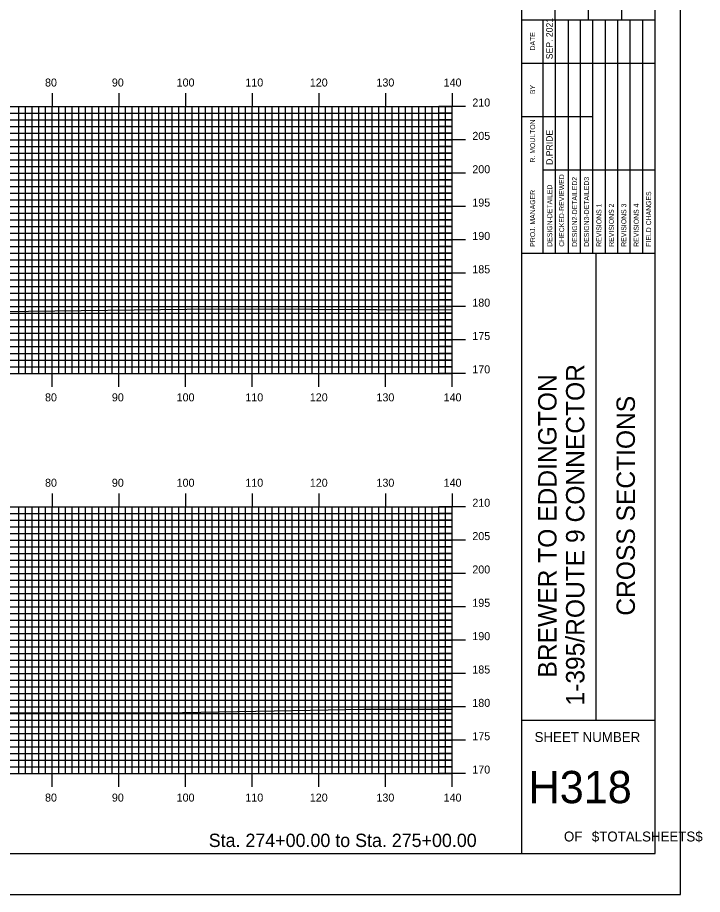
# Model space of a CAD drawing. Extents: x 1809406 to 1809749, y 442591 to 442811.
# Drawn here: x 1809646.7 to 1809749.3, y 442590.5 to 442722 of the extents above; entities that cross this region are included whole.
import ezdxf

# ---------------------------------------------------------------- set-up
doc = ezdxf.new("R2010")
doc.units = 0
for name, color, linetype in [('BORDER', 7, 'Continuous'), ('H_V ANNOTATION', 7, 'Continuous'), ('MAJOR', 7, 'Continuous'), ('MINOR', 7, 'Continuous'), ('PLOT BOUNDARY', 7, 'Continuous'), ('S_Roadway_Centerline', 7, 'Continuous')]:
    doc.layers.add(name, color=color, linetype=linetype)

msp = doc.modelspace()

# ---------------------------------------------------------------- linework, layer by layer
at = {"layer": 'BORDER'}
for p, q in [((1809722.24, 442596.67), (1809722.24, 442806.67)), ((1809727.24, 442721.67), (1809727.24, 442738.97)), ((1809732.24, 442721.67), (1809732.24, 442738.97)), ((1809737.24, 442721.67), (1809737.24, 442738.97)), ((1809722.24, 442721.67), (1809742.24, 442721.67)), ((1809722.24, 442686.67), (1809742.24, 442686.67)), ((1809733.42, 442616.67), (1809733.42, 442686.67)), ((1809722.24, 442616.67), (1809742.24, 442616.67))]:
    msp.add_line(p, q, dxfattribs=at)
msp.add_lwpolyline([(1809422.24, 442596.67), (1809742.24, 442596.67), (1809742.24, 442806.67), (1809422.24, 442806.67)], close=True, dxfattribs=at)
for points in [[(1809725.47, 442715.17), (1809725.47, 442721.67)], [(1809727.33, 442686.68), (1809727.33, 442721.67)], [(1809729.2, 442721.67), (1809729.2, 442686.68)], [(1809731.06, 442686.68), (1809731.06, 442721.67)], [(1809732.92, 442686.68), (1809732.92, 442721.67)], [(1809734.79, 442686.68), (1809734.79, 442721.67)], [(1809736.65, 442686.68), (1809736.65, 442721.67)], [(1809738.51, 442686.68), (1809738.51, 442721.67)], [(1809740.38, 442686.68), (1809740.38, 442721.67)], [(1809725.47, 442686.68), (1809725.47, 442720.26)], [(1809722.24, 442715.17), (1809742.24, 442715.17)], [(1809722.24, 442707.17), (1809725.47, 442707.17)], [(1809725.47, 442707.17), (1809732.92, 442707.17)], [(1809725.47, 442699.17), (1809742.24, 442699.17)]]:
    msp.add_lwpolyline(points, dxfattribs=at)
at = {"layer": 'MAJOR'}
for p, q in [((1809651.84, 442710.67), (1809651.84, 442708.67)), ((1809661.84, 442710.67), (1809661.84, 442708.67)), ((1809671.84, 442710.67), (1809671.84, 442708.67)), ((1809681.84, 442710.67), (1809681.84, 442708.67)), ((1809691.84, 442710.67), (1809691.84, 442708.67)), ((1809701.84, 442710.67), (1809701.84, 442708.67)), ((1809711.84, 442710.67), (1809711.84, 442708.67)), ((1809431.84, 442708.67), (1809711.84, 442708.67)), ((1809431.84, 442708.67), (1809711.84, 442708.67)), ((1809651.84, 442668.67), (1809651.84, 442708.67)), ((1809661.84, 442668.67), (1809661.84, 442708.67)), ((1809671.84, 442668.67), (1809671.84, 442708.67)), ((1809681.84, 442668.67), (1809681.84, 442708.67)), ((1809691.84, 442668.67), (1809691.84, 442708.67)), ((1809701.84, 442668.67), (1809701.84, 442708.67)), ((1809713.84, 442708.67), (1809709.83, 442708.67)), ((1809711.84, 442668.67), (1809711.84, 442708.67)), ((1809711.84, 442668.67), (1809711.84, 442708.67)), ((1809431.84, 442703.67), (1809711.84, 442703.67)), ((1809713.84, 442703.67), (1809709.83, 442703.67)), ((1809431.84, 442698.67), (1809711.84, 442698.67)), ((1809713.84, 442698.67), (1809709.83, 442698.67)), ((1809431.84, 442693.67), (1809711.84, 442693.67)), ((1809713.84, 442693.67), (1809709.83, 442693.67)), ((1809431.84, 442688.67), (1809711.84, 442688.67)), ((1809713.84, 442688.67), (1809709.83, 442688.67)), ((1809431.84, 442683.67), (1809711.84, 442683.67)), ((1809713.84, 442683.67), (1809709.83, 442683.67)), ((1809431.84, 442678.67), (1809711.84, 442678.67)), ((1809713.84, 442678.67), (1809709.83, 442678.67)), ((1809431.84, 442673.67), (1809711.84, 442673.67)), ((1809713.84, 442673.67), (1809709.83, 442673.67)), ((1809431.84, 442668.67), (1809711.84, 442668.67)), ((1809431.84, 442668.67), (1809711.84, 442668.67)), ((1809651.84, 442666.66), (1809651.84, 442668.67)), ((1809661.84, 442666.66), (1809661.84, 442668.67)), ((1809671.84, 442666.66), (1809671.84, 442668.67)), ((1809681.84, 442666.66), (1809681.84, 442668.67)), ((1809691.84, 442666.66), (1809691.84, 442668.67)), ((1809701.84, 442666.66), (1809701.84, 442668.67)), ((1809713.84, 442668.67), (1809709.83, 442668.67)), ((1809711.84, 442666.66), (1809711.84, 442668.67)), ((1809651.84, 442650.67), (1809651.84, 442648.67)), ((1809661.84, 442650.67), (1809661.84, 442648.67)), ((1809671.84, 442650.67), (1809671.84, 442648.67)), ((1809681.84, 442650.67), (1809681.84, 442648.67)), ((1809691.84, 442650.67), (1809691.84, 442648.67)), ((1809701.84, 442650.67), (1809701.84, 442648.67)), ((1809711.84, 442650.67), (1809711.84, 442648.67)), ((1809431.84, 442648.67), (1809711.84, 442648.67)), ((1809431.84, 442648.67), (1809711.84, 442648.67)), ((1809651.84, 442608.67), (1809651.84, 442648.67)), ((1809661.84, 442608.67), (1809661.84, 442648.67)), ((1809671.84, 442608.67), (1809671.84, 442648.67)), ((1809681.84, 442608.67), (1809681.84, 442648.67)), ((1809691.84, 442608.67), (1809691.84, 442648.67)), ((1809701.84, 442608.67), (1809701.84, 442648.67)), ((1809713.84, 442648.67), (1809709.83, 442648.67)), ((1809711.84, 442608.67), (1809711.84, 442648.67)), ((1809711.84, 442608.67), (1809711.84, 442648.67)), ((1809431.84, 442643.67), (1809711.84, 442643.67)), ((1809713.84, 442643.67), (1809709.83, 442643.67)), ((1809431.84, 442638.67), (1809711.84, 442638.67)), ((1809713.84, 442638.67), (1809709.83, 442638.67)), ((1809431.84, 442633.67), (1809711.84, 442633.67)), ((1809713.84, 442633.67), (1809709.83, 442633.67)), ((1809431.84, 442628.67), (1809711.84, 442628.67)), ((1809713.84, 442628.67), (1809709.83, 442628.67)), ((1809431.84, 442623.67), (1809711.84, 442623.67)), ((1809713.84, 442623.67), (1809709.83, 442623.67)), ((1809431.84, 442618.67), (1809711.84, 442618.67)), ((1809713.84, 442618.67), (1809709.83, 442618.67)), ((1809431.84, 442613.67), (1809711.84, 442613.67)), ((1809713.84, 442613.67), (1809709.83, 442613.67)), ((1809431.84, 442608.67), (1809711.84, 442608.67)), ((1809431.84, 442608.67), (1809711.84, 442608.67)), ((1809651.84, 442606.66), (1809651.84, 442608.67)), ((1809661.84, 442606.66), (1809661.84, 442608.67)), ((1809671.84, 442606.66), (1809671.84, 442608.67)), ((1809681.84, 442606.66), (1809681.84, 442608.67)), ((1809691.84, 442606.66), (1809691.84, 442608.67)), ((1809701.84, 442606.66), (1809701.84, 442608.67)), ((1809713.84, 442608.67), (1809709.83, 442608.67)), ((1809711.84, 442606.66), (1809711.84, 442608.67))]:
    msp.add_line(p, q, dxfattribs=at)
at = {"layer": 'MINOR'}
for p, q in [((1809646.84, 442668.67), (1809646.84, 442708.67)), ((1809647.84, 442668.67), (1809647.84, 442708.67)), ((1809648.84, 442668.67), (1809648.84, 442708.67)), ((1809649.84, 442668.67), (1809649.84, 442708.67)), ((1809650.84, 442668.67), (1809650.84, 442708.67)), ((1809652.84, 442668.67), (1809652.84, 442708.67)), ((1809653.84, 442668.67), (1809653.84, 442708.67)), ((1809654.84, 442668.67), (1809654.84, 442708.67)), ((1809655.84, 442668.67), (1809655.84, 442708.67)), ((1809656.84, 442668.67), (1809656.84, 442708.67)), ((1809657.84, 442668.67), (1809657.84, 442708.67)), ((1809658.84, 442668.67), (1809658.84, 442708.67)), ((1809659.84, 442668.67), (1809659.84, 442708.67)), ((1809660.84, 442668.67), (1809660.84, 442708.67)), ((1809662.84, 442668.67), (1809662.84, 442708.67)), ((1809663.84, 442668.67), (1809663.84, 442708.67)), ((1809664.84, 442668.67), (1809664.84, 442708.67)), ((1809665.84, 442668.67), (1809665.84, 442708.67)), ((1809666.84, 442668.67), (1809666.84, 442708.67)), ((1809667.84, 442668.67), (1809667.84, 442708.67)), ((1809668.84, 442668.67), (1809668.84, 442708.67)), ((1809669.84, 442668.67), (1809669.84, 442708.67)), ((1809670.84, 442668.67), (1809670.84, 442708.67)), ((1809672.84, 442668.67), (1809672.84, 442708.67)), ((1809673.84, 442668.67), (1809673.84, 442708.67)), ((1809674.84, 442668.67), (1809674.84, 442708.67)), ((1809675.84, 442668.67), (1809675.84, 442708.67)), ((1809676.84, 442668.67), (1809676.84, 442708.67)), ((1809677.84, 442668.67), (1809677.84, 442708.67)), ((1809678.84, 442668.67), (1809678.84, 442708.67)), ((1809679.84, 442668.67), (1809679.84, 442708.67)), ((1809680.84, 442668.67), (1809680.84, 442708.67)), ((1809682.84, 442668.67), (1809682.84, 442708.67)), ((1809683.84, 442668.67), (1809683.84, 442708.67)), ((1809684.84, 442668.67), (1809684.84, 442708.67)), ((1809685.84, 442668.67), (1809685.84, 442708.67)), ((1809686.84, 442668.67), (1809686.84, 442708.67)), ((1809687.84, 442668.67), (1809687.84, 442708.67)), ((1809688.84, 442668.67), (1809688.84, 442708.67)), ((1809689.84, 442668.67), (1809689.84, 442708.67)), ((1809690.84, 442668.67), (1809690.84, 442708.67)), ((1809692.84, 442668.67), (1809692.84, 442708.67)), ((1809693.84, 442668.67), (1809693.84, 442708.67)), ((1809694.84, 442668.67), (1809694.84, 442708.67)), ((1809695.84, 442668.67), (1809695.84, 442708.67)), ((1809696.84, 442668.67), (1809696.84, 442708.67)), ((1809697.84, 442668.67), (1809697.84, 442708.67)), ((1809698.84, 442668.67), (1809698.84, 442708.67)), ((1809699.84, 442668.67), (1809699.84, 442708.67)), ((1809700.84, 442668.67), (1809700.84, 442708.67)), ((1809702.84, 442668.67), (1809702.84, 442708.67)), ((1809703.84, 442668.67), (1809703.84, 442708.67)), ((1809704.84, 442668.67), (1809704.84, 442708.67)), ((1809705.84, 442668.67), (1809705.84, 442708.67)), ((1809706.84, 442668.67), (1809706.84, 442708.67)), ((1809707.84, 442668.67), (1809707.84, 442708.67)), ((1809708.84, 442668.67), (1809708.84, 442708.67)), ((1809709.84, 442668.67), (1809709.84, 442708.67)), ((1809710.84, 442668.67), (1809710.84, 442708.67)), ((1809431.84, 442707.67), (1809711.84, 442707.67)), ((1809711.84, 442707.67), (1809709.83, 442707.67)), ((1809431.84, 442706.67), (1809711.84, 442706.67)), ((1809431.84, 442705.67), (1809711.84, 442705.67)), ((1809711.84, 442706.67), (1809709.83, 442706.67)), ((1809711.84, 442705.67), (1809709.83, 442705.67)), ((1809431.84, 442704.67), (1809711.84, 442704.67)), ((1809711.84, 442704.67), (1809709.83, 442704.67)), ((1809431.84, 442702.67), (1809711.84, 442702.67)), ((1809431.84, 442701.67), (1809711.84, 442701.67)), ((1809711.84, 442702.67), (1809709.83, 442702.67)), ((1809711.84, 442701.67), (1809709.83, 442701.67)), ((1809431.84, 442700.67), (1809711.84, 442700.67)), ((1809711.84, 442700.67), (1809709.83, 442700.67)), ((1809431.84, 442699.67), (1809711.84, 442699.67)), ((1809711.84, 442699.67), (1809709.83, 442699.67)), ((1809431.84, 442697.67), (1809711.84, 442697.67)), ((1809711.84, 442697.67), (1809709.83, 442697.67)), ((1809431.84, 442696.67), (1809711.84, 442696.67)), ((1809711.84, 442696.67), (1809709.83, 442696.67)), ((1809431.84, 442695.67), (1809711.84, 442695.67)), ((1809711.84, 442695.67), (1809709.83, 442695.67)), ((1809431.84, 442694.67), (1809711.84, 442694.67)), ((1809711.84, 442694.67), (1809709.83, 442694.67)), ((1809431.84, 442692.67), (1809711.84, 442692.67)), ((1809711.84, 442692.67), (1809709.83, 442692.67)), ((1809431.84, 442691.67), (1809711.84, 442691.67)), ((1809711.84, 442691.67), (1809709.83, 442691.67)), ((1809431.84, 442690.67), (1809711.84, 442690.67)), ((1809711.84, 442690.67), (1809709.83, 442690.67)), ((1809431.84, 442689.67), (1809711.84, 442689.67)), ((1809711.84, 442689.67), (1809709.83, 442689.67)), ((1809431.84, 442687.67), (1809711.84, 442687.67)), ((1809711.84, 442687.67), (1809709.83, 442687.67)), ((1809431.84, 442686.67), (1809711.84, 442686.67)), ((1809711.84, 442686.67), (1809709.83, 442686.67)), ((1809431.84, 442685.67), (1809711.84, 442685.67)), ((1809431.84, 442684.67), (1809711.84, 442684.67)), ((1809711.84, 442685.67), (1809709.83, 442685.67)), ((1809711.84, 442684.67), (1809709.83, 442684.67)), ((1809431.84, 442682.67), (1809711.84, 442682.67)), ((1809711.84, 442682.67), (1809709.83, 442682.67)), ((1809431.84, 442681.67), (1809711.84, 442681.67)), ((1809431.84, 442680.67), (1809711.84, 442680.67)), ((1809711.84, 442681.67), (1809709.83, 442681.67)), ((1809711.84, 442680.67), (1809709.83, 442680.67)), ((1809431.84, 442679.67), (1809711.84, 442679.67)), ((1809711.84, 442679.67), (1809709.83, 442679.67)), ((1809431.84, 442677.67), (1809711.84, 442677.67)), ((1809431.84, 442676.67), (1809711.84, 442676.67)), ((1809711.84, 442677.67), (1809709.83, 442677.67)), ((1809711.84, 442676.67), (1809709.83, 442676.67)), ((1809431.84, 442675.67), (1809711.84, 442675.67)), ((1809711.84, 442675.67), (1809709.83, 442675.67)), ((1809431.84, 442674.67), (1809711.84, 442674.67)), ((1809711.84, 442674.67), (1809709.83, 442674.67)), ((1809431.84, 442672.67), (1809711.84, 442672.67)), ((1809711.84, 442672.67), (1809709.83, 442672.67)), ((1809431.84, 442671.67), (1809711.84, 442671.67)), ((1809711.84, 442671.67), (1809709.83, 442671.67)), ((1809431.84, 442670.67), (1809711.84, 442670.67)), ((1809711.84, 442670.67), (1809709.83, 442670.67)), ((1809431.84, 442669.67), (1809711.84, 442669.67)), ((1809711.84, 442669.67), (1809709.83, 442669.67)), ((1809431.84, 442647.67), (1809711.84, 442647.67)), ((1809646.84, 442608.67), (1809646.84, 442648.67)), ((1809647.84, 442608.67), (1809647.84, 442648.67)), ((1809648.84, 442608.67), (1809648.84, 442648.67)), ((1809649.84, 442608.67), (1809649.84, 442648.67)), ((1809650.84, 442608.67), (1809650.84, 442648.67)), ((1809652.84, 442608.67), (1809652.84, 442648.67)), ((1809653.84, 442608.67), (1809653.84, 442648.67)), ((1809654.84, 442608.67), (1809654.84, 442648.67)), ((1809655.84, 442608.67), (1809655.84, 442648.67)), ((1809656.84, 442608.67), (1809656.84, 442648.67)), ((1809657.84, 442608.67), (1809657.84, 442648.67)), ((1809658.84, 442608.67), (1809658.84, 442648.67)), ((1809659.84, 442608.67), (1809659.84, 442648.67)), ((1809660.84, 442608.67), (1809660.84, 442648.67)), ((1809662.84, 442608.67), (1809662.84, 442648.67)), ((1809663.84, 442608.67), (1809663.84, 442648.67)), ((1809664.84, 442608.67), (1809664.84, 442648.67)), ((1809665.84, 442608.67), (1809665.84, 442648.67)), ((1809666.84, 442608.67), (1809666.84, 442648.67)), ((1809667.84, 442608.67), (1809667.84, 442648.67)), ((1809668.84, 442608.67), (1809668.84, 442648.67)), ((1809669.84, 442608.67), (1809669.84, 442648.67)), ((1809670.84, 442608.67), (1809670.84, 442648.67)), ((1809672.84, 442608.67), (1809672.84, 442648.67)), ((1809673.84, 442608.67), (1809673.84, 442648.67)), ((1809674.84, 442608.67), (1809674.84, 442648.67)), ((1809675.84, 442608.67), (1809675.84, 442648.67)), ((1809676.84, 442608.67), (1809676.84, 442648.67)), ((1809677.84, 442608.67), (1809677.84, 442648.67)), ((1809678.84, 442608.67), (1809678.84, 442648.67)), ((1809679.84, 442608.67), (1809679.84, 442648.67)), ((1809680.84, 442608.67), (1809680.84, 442648.67)), ((1809682.84, 442608.67), (1809682.84, 442648.67)), ((1809683.84, 442608.67), (1809683.84, 442648.67)), ((1809684.84, 442608.67), (1809684.84, 442648.67)), ((1809685.84, 442608.67), (1809685.84, 442648.67)), ((1809686.84, 442608.67), (1809686.84, 442648.67)), ((1809687.84, 442608.67), (1809687.84, 442648.67)), ((1809688.84, 442608.67), (1809688.84, 442648.67)), ((1809689.84, 442608.67), (1809689.84, 442648.67)), ((1809690.84, 442608.67), (1809690.84, 442648.67)), ((1809692.84, 442608.67), (1809692.84, 442648.67)), ((1809693.84, 442608.67), (1809693.84, 442648.67)), ((1809694.84, 442608.67), (1809694.84, 442648.67)), ((1809695.84, 442608.67), (1809695.84, 442648.67)), ((1809696.84, 442608.67), (1809696.84, 442648.67)), ((1809697.84, 442608.67), (1809697.84, 442648.67)), ((1809698.84, 442608.67), (1809698.84, 442648.67)), ((1809699.84, 442608.67), (1809699.84, 442648.67)), ((1809700.84, 442608.67), (1809700.84, 442648.67)), ((1809702.84, 442608.67), (1809702.84, 442648.67)), ((1809703.84, 442608.67), (1809703.84, 442648.67)), ((1809704.84, 442608.67), (1809704.84, 442648.67)), ((1809705.84, 442608.67), (1809705.84, 442648.67)), ((1809706.84, 442608.67), (1809706.84, 442648.67)), ((1809707.84, 442608.67), (1809707.84, 442648.67)), ((1809708.84, 442608.67), (1809708.84, 442648.67)), ((1809711.84, 442647.67), (1809709.83, 442647.67)), ((1809709.84, 442608.67), (1809709.84, 442648.67)), ((1809710.84, 442608.67), (1809710.84, 442648.67)), ((1809431.84, 442646.67), (1809711.84, 442646.67)), ((1809711.84, 442646.67), (1809709.83, 442646.67)), ((1809431.84, 442645.67), (1809711.84, 442645.67)), ((1809711.84, 442645.67), (1809709.83, 442645.67)), ((1809431.84, 442644.67), (1809711.84, 442644.67)), ((1809711.84, 442644.67), (1809709.83, 442644.67)), ((1809431.84, 442642.67), (1809711.84, 442642.67)), ((1809711.84, 442642.67), (1809709.83, 442642.67)), ((1809431.84, 442641.67), (1809711.84, 442641.67)), ((1809711.84, 442641.67), (1809709.83, 442641.67)), ((1809431.84, 442640.67), (1809711.84, 442640.67)), ((1809711.84, 442640.67), (1809709.83, 442640.67)), ((1809431.84, 442639.67), (1809711.84, 442639.67)), ((1809711.84, 442639.67), (1809709.83, 442639.67)), ((1809431.84, 442637.67), (1809711.84, 442637.67)), ((1809711.84, 442637.67), (1809709.83, 442637.67)), ((1809431.84, 442636.67), (1809711.84, 442636.67)), ((1809711.84, 442636.67), (1809709.83, 442636.67)), ((1809431.84, 442635.67), (1809711.84, 442635.67)), ((1809431.84, 442634.67), (1809711.84, 442634.67)), ((1809711.84, 442635.67), (1809709.83, 442635.67)), ((1809711.84, 442634.67), (1809709.83, 442634.67)), ((1809431.84, 442632.67), (1809711.84, 442632.67)), ((1809711.84, 442632.67), (1809709.83, 442632.67)), ((1809431.84, 442631.67), (1809711.84, 442631.67)), ((1809431.84, 442630.67), (1809711.84, 442630.67)), ((1809711.84, 442631.67), (1809709.83, 442631.67)), ((1809711.84, 442630.67), (1809709.83, 442630.67)), ((1809431.84, 442629.67), (1809711.84, 442629.67)), ((1809711.84, 442629.67), (1809709.83, 442629.67)), ((1809431.84, 442627.67), (1809711.84, 442627.67)), ((1809431.84, 442626.67), (1809711.84, 442626.67)), ((1809711.84, 442627.67), (1809709.83, 442627.67)), ((1809711.84, 442626.67), (1809709.83, 442626.67)), ((1809431.84, 442625.67), (1809711.84, 442625.67)), ((1809711.84, 442625.67), (1809709.83, 442625.67)), ((1809431.84, 442624.67), (1809711.84, 442624.67)), ((1809711.84, 442624.67), (1809709.83, 442624.67)), ((1809431.84, 442622.67), (1809711.84, 442622.67)), ((1809711.84, 442622.67), (1809709.83, 442622.67)), ((1809431.84, 442621.67), (1809711.84, 442621.67)), ((1809711.84, 442621.67), (1809709.83, 442621.67)), ((1809431.84, 442620.67), (1809711.84, 442620.67)), ((1809711.84, 442620.67), (1809709.83, 442620.67)), ((1809431.84, 442619.67), (1809711.84, 442619.67)), ((1809711.84, 442619.67), (1809709.83, 442619.67)), ((1809431.84, 442617.67), (1809711.84, 442617.67)), ((1809711.84, 442617.67), (1809709.83, 442617.67)), ((1809431.84, 442616.67), (1809711.84, 442616.67)), ((1809711.84, 442616.67), (1809709.83, 442616.67)), ((1809431.84, 442615.67), (1809711.84, 442615.67)), ((1809711.84, 442615.67), (1809709.83, 442615.67)), ((1809431.84, 442614.67), (1809711.84, 442614.67)), ((1809711.84, 442614.67), (1809709.83, 442614.67)), ((1809431.84, 442612.67), (1809711.84, 442612.67)), ((1809711.84, 442612.67), (1809709.83, 442612.67)), ((1809431.84, 442611.67), (1809711.84, 442611.67)), ((1809711.84, 442611.67), (1809709.83, 442611.67)), ((1809431.84, 442610.67), (1809711.84, 442610.67)), ((1809431.84, 442609.67), (1809711.84, 442609.67)), ((1809711.84, 442610.67), (1809709.83, 442610.67)), ((1809711.84, 442609.67), (1809709.83, 442609.67))]:
    msp.add_line(p, q, dxfattribs=at)
at = {"layer": 'PLOT BOUNDARY'}
msp.add_lwpolyline([(1809406.05, 442590.55), (1809746.05, 442590.55), (1809746.05, 442810.55), (1809406.05, 442810.55)], close=True, dxfattribs=at)
at = {"layer": 'S_Roadway_Centerline'}
for points in [[(1809538.25, 442677.36), (1809553.38, 442677.19), (1809568.97, 442677.27), (1809572.62, 442677.47), (1809585.01, 442677.4), (1809620.74, 442677.67), (1809622.01, 442677.68), (1809622.58, 442677.69), (1809624.52, 442677.7), (1809672.05, 442678.29), (1809680.89, 442678.33), (1809700.54, 442678.23), (1809711.84, 442678.21)], [(1809531.99, 442616.66), (1809543.3, 442616.68), (1809550.95, 442616.68), (1809554.3, 442616.9), (1809555.63, 442617.14), (1809566.24, 442617.71), (1809566.6, 442617.74), (1809574.95, 442618.17), (1809582.08, 442617.78), (1809588.51, 442617.57), (1809630.2, 442617.59), (1809643.64, 442617.83), (1809668.67, 442617.8), (1809687.86, 442618.11), (1809698.57, 442618.34), (1809711.84, 442618.34)]]:
    msp.add_lwpolyline(points, dxfattribs=at)

# ---------------------------------------------------------------- texts
at = {"layer": 'BORDER'}
for s, height, p in [('SEP. 2021', 0.969, (1809726.88, 442715.76)), ('DATE', 0.743, (1809724.25, 442717.08)), ('BY', 0.743, (1809724.25, 442710.54)), ('R. MOULTON', 0.745, (1809724.25, 442700.28)), ('D.PRIDE', 0.969, (1809726.88, 442699.92)), ('CHECKED-REVIEWED', 0.7455, (1809728.6, 442687.65)), ('DESIGN2-DETAILED2', 0.7455, (1809730.54, 442687.65)), ('DESIGN3-DETAILED3', 0.7455, (1809732.33, 442687.65)), ('DESIGN-DETAILED', 0.7455, (1809726.81, 442687.65)), ('PROJ. MANAGER', 0.7455, (1809724.25, 442687.65)), ('FIELD CHANGES', 0.7455, (1809741.64, 442687.65)), ('REVISIONS 1', 0.7455, (1809734.19, 442687.65)), ('REVISIONS 2', 0.7455, (1809736.05, 442687.65)), ('REVISIONS 3', 0.7455, (1809737.92, 442687.65)), ('REVISIONS 4', 0.7455, (1809739.78, 442687.65)), ('1-395/ROUTE 9 CONNECTOR', 2.7557, (1809731.64, 442618.87)), ('BREWER TO EDDINGTON', 2.7557, (1809727.46, 442623.07)), ('CROSS SECTIONS', 2.7557, (1809739.21, 442632.34))]:
    msp.add_text(s, height=height, rotation=90, dxfattribs=at).set_placement(p)
for s, height, p in [('SHEET NUMBER', 1.4905, (1809724.17, 442613.4)), ('H318', 4.839, (1809723.27, 442604.23)), ('OF', 1.491, (1809728.57, 442598.49)), ('$TOTALSHEETS$', 1.4905, (1809732.75, 442598.49))]:
    msp.add_text(s, height=height, dxfattribs=at).set_placement(p)
at = {"layer": 'H_V ANNOTATION'}
for s, height, p in [('80', 1.2, (1809650.79, 442711.67)), ('90', 1.2, (1809660.81, 442711.67)), ('100', 1.2, (1809670.52, 442711.67)), ('110', 1.2, (1809680.82, 442711.67)), ('120', 1.2, (1809690.48, 442711.67)), ('130', 1.2, (1809700.47, 442711.67)), ('140', 1.2, (1809710.54, 442711.67)), ('210', 1.2, (1809714.84, 442708.67)), ('205', 1.2, (1809714.84, 442703.67)), ('200', 1.2, (1809714.84, 442698.67)), ('195', 1.2, (1809714.84, 442693.67)), ('190', 1.2, (1809714.84, 442688.67)), ('185', 1.2, (1809714.84, 442683.67)), ('180', 1.2, (1809714.84, 442678.67)), ('175', 1.2, (1809714.84, 442673.67)), ('170', 1.2, (1809714.84, 442668.67)), ('80', 1.2, (1809650.79, 442664.47)), ('90', 1.2, (1809660.81, 442664.47)), ('100', 1.2, (1809670.52, 442664.47)), ('110', 1.2, (1809680.82, 442664.47)), ('120', 1.2, (1809690.48, 442664.47)), ('130', 1.2, (1809700.47, 442664.47)), ('140', 1.2, (1809710.54, 442664.47)), ('80', 1.2, (1809650.79, 442651.67)), ('90', 1.2, (1809660.81, 442651.67)), ('100', 1.2, (1809670.52, 442651.67)), ('110', 1.2, (1809680.82, 442651.67)), ('120', 1.2, (1809690.48, 442651.67)), ('130', 1.2, (1809700.47, 442651.67)), ('140', 1.2, (1809710.54, 442651.67)), ('210', 1.2, (1809714.84, 442648.67)), ('205', 1.2, (1809714.84, 442643.67)), ('200', 1.2, (1809714.84, 442638.67)), ('195', 1.2, (1809714.84, 442633.67)), ('190', 1.2, (1809714.84, 442628.67)), ('185', 1.2, (1809714.84, 442623.67)), ('180', 1.2, (1809714.84, 442618.67)), ('175', 1.2, (1809714.84, 442613.67)), ('170', 1.2, (1809714.84, 442608.67)), ('80', 1.2, (1809650.79, 442604.47)), ('90', 1.2, (1809660.81, 442604.47)), ('100', 1.2, (1809670.52, 442604.47)), ('110', 1.2, (1809680.82, 442604.47)), ('120', 1.2, (1809690.48, 442604.47)), ('130', 1.2, (1809700.47, 442604.47)), ('140', 1.2, (1809710.54, 442604.47)), ('Sta. 274+00.00 to Sta. 275+00.00', 2.0004, (1809675.33, 442597.66))]:
    msp.add_text(s, height=height, dxfattribs=at).set_placement(p)

doc.saveas('drawing.dxf')
